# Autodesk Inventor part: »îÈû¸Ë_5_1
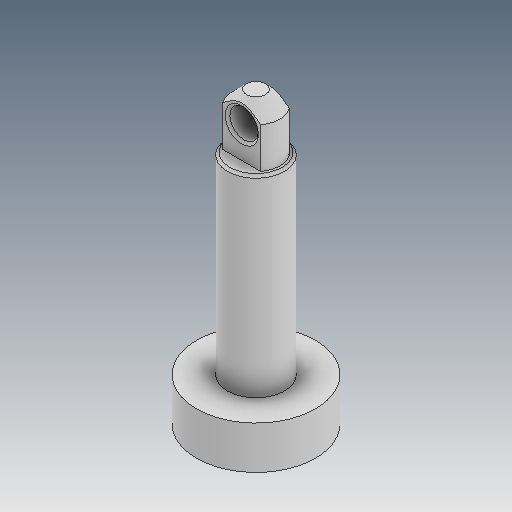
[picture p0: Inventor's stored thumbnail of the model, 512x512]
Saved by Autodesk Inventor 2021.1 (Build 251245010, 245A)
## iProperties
Created: 2019-04
Part Number: »îÈû¸Ë_5_1
Material: Ogólny
Document SubType Name: Modeling
Designer: user
Density: 1 g/cm^3
Appearance: Domyślna
Author: user
Revision Number: ÈÎºÎ
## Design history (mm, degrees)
feature "ÊäÈë1"
node "Bryła1"
